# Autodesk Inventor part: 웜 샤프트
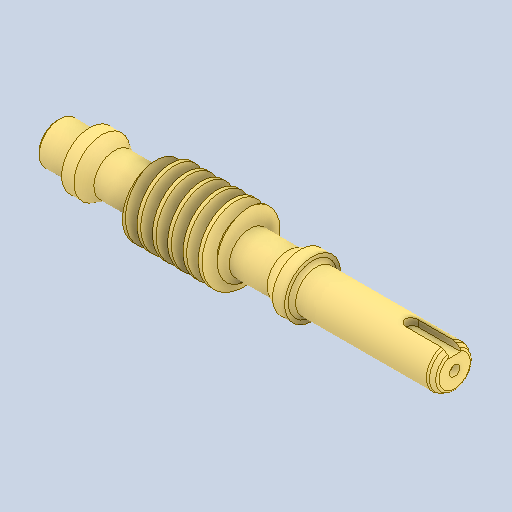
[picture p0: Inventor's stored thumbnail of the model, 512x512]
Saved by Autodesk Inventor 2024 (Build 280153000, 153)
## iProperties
Created: 2026-01
Part Number: 웜 샤프트
Material: 강철, 합금
Document SubType Name: Modeling
Designer: 2-10
Density: 7.73 g/cm^3
Appearance: 기본값
Sending System: Autodesk Inventor 2026
Preprocessor: ST-DEVELOPER v20.1
Author: jhkim
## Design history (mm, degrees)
node "웜 샤프트1"
node "솔리드2"
node "솔리드1"
